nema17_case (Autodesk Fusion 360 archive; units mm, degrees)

design "final_assemble_winch+nemacase" references "Nema 17-1", "winch_final"
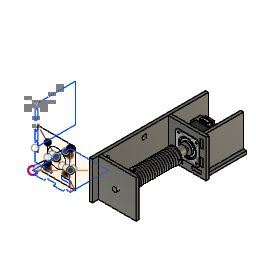
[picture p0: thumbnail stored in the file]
sketch "Sketch1" plane through (0, 0, 0) normal (0, 1, 0) x axis (1, 0, 0)
  line L1 (-32.5, 32.5) -> (32.5, 32.5)
  line L2 (32.5, -32.5) -> (-32.5, -32.5)
  line L3 (32.5, 32.5) -> (32.5, -32.5)
  line L4 (-32.5, -32.5) -> (32.5, 32.5)
  line L5 (32.5, -32.5) -> (-32.5, 32.5)
  line L6 (-15.5, -15.5) -> (-15.5, 0)
  line L7 (0, -3) -> (0, 0)
  line L8 (-3.2, 0) -> (0, 0)
  line L9 (-37.5, -24.375) -> (-32.5, -24.375)
  line L10 (-37.5, -8.125) -> (-37.5, -24.375)
  line L11 (-32.5, -8.125) -> (-37.5, -8.125)
  line L12 (-37.5, 8.125) -> (-37.5, 24.375)
  line L13 (-37.5, 24.375) -> (-32.5, 24.375)
  line L14 (-32.5, 8.125) -> (-37.5, 8.125)
  line L15 (22.5, -15.5) -> (15.5, -15.5)
  line L16 (22.5, 32.5) -> (22.5, -32.5)
  line L17 (-15.5, 22.5) -> (-15.5, 15.5)
  line L18 (-32.5, -32.5) -> (-32.5, -24.375)
  line L19 (-32.5, 24.375) -> (-32.5, 32.5)
  line L20 (-32.5, -8.125) -> (-32.5, 8.125)
  circle C1 centre (0, 0) radius 15.5
  circle C2 centre (-15.5, -15.5) radius 1.5
  circle C3 centre (-15.5, 15.5) radius 1.5
  circle C4 centre (15.5, 15.5) radius 1.5
  circle C5 centre (15.5, -15.5) radius 1.5
  point P6 (0, 0)
  point P1 (0, 0)
  point P7 (0, 0)
  point P8 (-15.5, 0)
  point P9 (-15.5, -15.5)
  point P10 (-15.5, -15.5)
  point P11 (0, 0)
  point P13 (0, 0)
  point P18 (-32.5, -24.375)
  point P24 (-32.5, 24.375)
  point P19 (-37.5, -24.375)
  point P22 (-37.5, 24.375)
  point P20 (-37.5, -8.125)
  point P23 (-37.5, 8.125)
  point P21 (-32.5, -8.125)
  point P25 (-32.5, 8.125)
  point P17 (15.5, -15.5)
  point P26 (15.5, -15.5)
  point P28 (22.5, -32.5)
  point P29 (22.5, 32.5)
  point P15 (-15.5, 15.5)
  point P30 (-15.5, 15.5)
  point P4 (-32.5, -32.5)
  point P5 (32.5, -32.5)
  point P2 (32.5, 32.5)
  point P27 (22.5, -15.5)
  point P3 (-32.5, 32.5)
  point P31 (-15.5, 22.5)
  perpendicular L1 L19
  parallel L1 L2
  parallel L3 L19
  horizontal L1
  coincident L4 P6
  coincident L5 P6
  coincident P1 P6
  coincident P1 P7
  coincident C1 P8
  tangent C1 L6
  parallel L6 L19
  coincident P9 P10
  coincident P1 P11
  vertical L7
  coincident P1 P13
  perpendicular L7 L8
  symmetric C2 L8 C3
  symmetric L7 C3 C4
  symmetric C2 L7 C5
  coincident P18 L19
  perpendicular L9 L19
  perpendicular L9 L10
  perpendicular L11 L19
  symmetric L8 P18 P24
  symmetric L8 P19 P22
  symmetric L8 P20 P23
  symmetric L8 P21 P25
  coincident P17 P26
  horizontal L15
  coincident L2 P28
  coincident L1 P29
  perpendicular L1 L16
  coincident P15 P30
  vertical L17
  collinear L18 L19
  collinear L19 L20
  dimension "d1" distance P4 P5 = 65
  dimension "d2" distance P2 P5 = 65
  dimension "d3" diameter C1 = 31
  dimension "d4" distance P8 P9 = 15.5 (= "( 31 / 2 ) * 1 mm")
  dimension "d5" diameter C2 = 3
  dimension "d7" distance P19 P20 = 16.25
  dimension "d8" distance P26 P27 P3 = 7
  dimension "d9" distance P30 P31 = 7
  dimension "d27" distance P3 = 55
  dimension "d113" distance P3 = 4.4
extrude "Extrude4" new body sketch "Sketch1" profile of L1 L20 L2 L3 C1 L6 C2 C3 C4 C5 L9 L10 L11 L12 L13 L14 L15 L16 along normal blind 5
sketch "Sketch2" plane through (0, 0, 0) normal (0, 1, 0) x axis (1, 0, 0)
sketch "Sketch3" plane through (0, 0, 0) normal (0, 0, 1) x axis (1, 0, 0)
  line L1 (-2.1, 25.8) -> (-2.1, -39.2)
  line L2 (62.9, 25.8) -> (-2.1, 25.8)
  line L3 (62.9, -39.2) -> (62.9, 25.8)
  line L4 (-2.1, 25.8) -> (62.9, -39.2)
  line L5 (62.9, 25.8) -> (-2.1, -39.2)
  line L6 (22.275, -39.2) -> (22.275, -44.2)
  line L7 (6.025, -44.2) -> (22.275, -44.2)
  line L8 (6.025, -39.2) -> (6.025, -44.2)
  line L9 (54.775, -39.2) -> (54.775, -44.2)
  line L10 (54.775, -44.2) -> (38.525, -44.2)
  line L11 (38.525, -39.2) -> (38.525, -44.2)
  line L12 (54.775, -39.2) -> (62.9, -39.2)
  line L13 (22.275, -39.2) -> (38.525, -39.2)
  line L14 (-2.1, -39.2) -> (6.025, -39.2)
  point P6 (30.4, -6.7)
  point P8 (22.275, -39.2)
  point P10 (6.025, -39.2)
  point P4 (-2.1, 25.8)
  point P5 (62.9, 25.8)
  point P3 (-2.1, -39.2)
  point P7 (22.275, -44.2)
  point P9 (6.025, -44.2)
  perpendicular L1 L12
  parallel L2 L12
  parallel L1 L3
  horizontal L12
  coincident L4 P6
  coincident L5 P6
  coincident P8 L12
  perpendicular L6 L12
  perpendicular L6 L7
  coincident P10 L12
  perpendicular L8 L12
  collinear L12 L13
  collinear L13 L14
  dimension "d10" distance P4 P5 = 65
  dimension "d11" distance P3 P4 = 65
  dimension "d14" distance P7 P9 = 16.25
sketch "Sketch4" plane through (0, 0, 0) normal (0, 1, 0) x axis (1, 0, 0)
  line L1 (-8.125, 22.5) -> (-8.125, 27.15)
  line L2 (-24.375, 27.15) -> (-8.125, 27.15)
  line L3 (-24.375, 22.5) -> (-24.375, 27.15)
  line L4 (24.375, 22.5) -> (24.375, 27.15)
  line L5 (24.375, 27.15) -> (8.125, 27.15)
  line L6 (8.125, 22.5) -> (8.125, 27.15)
  line L7 (24.375, 22.5) -> (8.125, 22.5)
  line L8 (-24.375, 22.5) -> (-8.125, 22.5)
  point P2 (-8.125, 27.15)
  point P4 (-24.375, 27.15)
  perpendicular L1 L2
  perpendicular L1 L8
  dimension "d17" distance P2 P4 = 16.25
extrude "Extrude5" cut sketch "Sketch4" along normal blind 5
sketch "Sketch5" plane through (0, 0, 0) normal (0, 0, 1) x axis (1, 0, 0)
  line L1 (23.4, -6.7) -> (30.4, -6.7)
  line L2 (30.4, -1.9) -> (30.4, -6.7)
  line L3 (-8.5404, 1.425) -> (-8.5404, -6.7)
  line L4 (-2.1, 25.8) -> (-2.1, -39.2)
  line L5 (-7.1, 1.425) -> (-2.1, 1.425)
  line L6 (-7.1, 17.675) -> (-7.1, 1.425)
  line L7 (-2.1, 17.675) -> (-7.1, 17.675)
  line L8 (16.3, -6.7) -> (30.4, -6.7)
  line L9 (-2.1, -31.075) -> (-7.1, -31.075)
  line L10 (-7.1, -31.075) -> (-7.1, -14.825)
  line L11 (-7.1, -14.825) -> (-2.1, -14.825)
  line L12 (-2.1, 17.675) -> (-2.1, 25.8)
  line L13 (-2.1, -14.825) -> (-2.1, 1.425)
  point P2 (30.4, -6.7)
  point P3 (30.4, -6.7)
  point P5 (30.4, -6.7)
  point P11 (-2.1, 1.425)
  point P14 (-2.1, 17.675)
  point P19 (-2.1, -14.825)
  point P12 (-7.1, 1.425)
  point P18 (-7.1, -14.825)
  point P13 (-7.1, 17.675)
  point P16 (-7.1, -31.075)
  point P17 (-2.1, -31.075)
  point P10 (-2.1, 25.8)
  point P20 (-2.1, 25.8)
  point P7 (-8.5404, -6.7)
  point P8 (-8.5404, 1.425)
  coincident P2 P3
  horizontal L1
  coincident P2 P5
  perpendicular L1 L2
  perpendicular L1 L3
  coincident L4 P11
  perpendicular L3 L5
  perpendicular L5 L6
  coincident L4 P14
  perpendicular L4 L7
  perpendicular L2 L8
  symmetric P11 L8 P19
  symmetric P12 L8 P18
  symmetric P13 L8 P16
  symmetric P14 L8 P17
  coincident P10 P20
  collinear L12 L13
  dimension "d18" distance P7 P8 = 8.125
  dimension "d19" distance P11 P12 = 5
  dimension "d20" distance P12 P13 = 16.25
sketch "Sketch6" plane through (0, 0, 0) normal (1, 0, 0) x axis (0, 1, 0)
sketch "Sketch7" plane through (0, 0, 0) normal (0, 0, 1) x axis (1, 0, 0)
sketch "Sketch8" plane through (0, 0, 0) normal (1, 0, 0) x axis (0, 1, 0)
  line L1 (-32.4958, 33.4881) -> (32.5042, 33.4881)
  line L2 (32.5042, 98.4881) -> (-32.4958, 98.4881)
  line L3 (32.5042, 33.4881) -> (32.5042, 98.4881)
  line L4 (-37.1458, 33.4881) -> (-32.4958, 33.4881)
  line L5 (-32.4958, 98.4881) -> (-37.1458, 98.4881)
  line L6 (-37.1458, 74.1131) -> (-32.4958, 74.1131)
  line L7 (-37.1458, 90.3631) -> (-32.4958, 90.3631)
  line L8 (-37.1458, 57.8631) -> (-32.4958, 57.8631)
  line L9 (-37.1458, 41.6131) -> (-32.4958, 41.6131)
  line L10 (-32.4958, 57.8631) -> (-32.4958, 41.6131)
  line L11 (-32.4958, 90.3631) -> (-32.4958, 74.1131)
  line L12 (-37.1458, 57.8631) -> (-37.1458, 41.6131)
  line L13 (-37.1458, 90.3631) -> (-37.1458, 74.1131)
  point P8 (-32.4958, 74.1131)
  point P10 (-32.4958, 90.3631)
  point P11 (-37.1458, 90.3631)
  point P4 (-32.4958, 98.4881)
  point P5 (32.5042, 98.4881)
  point P3 (-32.4958, 33.4881)
  point P6 (-37.1458, 33.4881)
  point P7 (-37.1458, 98.4881)
  perpendicular L1 L10
  parallel L1 L2
  parallel L3 L10
  horizontal L1
  perpendicular L4 L10
  perpendicular L4 L12
  coincident P8 L10
  perpendicular L6 L12
  coincident P10 L10
  coincident P11 L12
  perpendicular L7 L12
  collinear L10 L11
  collinear L12 L13
  dimension "d21" distance P4 P5 = 65
  dimension "d22" distance P3 P4 = 65
  dimension "d23" distance P3 P6 = 4.65
  dimension "d24" distance P6 P7 = 65
sketch "Sketch9" plane through (0, 0, 0) normal (0, 1, 0) x axis (1, 0, 0)
sketch "Sketch10" plane through (0, 0.0042, 65.9881) normal (1, 0, 0) x axis (0, 1, 0)
  line L1 (32.5, 32.5) -> (-32.5, 32.5)
  line L2 (0, -22.5) -> (0, 32.5)
  line L3 (32.5, -32.5) -> (32.5, 32.5)
  line L4 (24.375, -22.5) -> (8.125, -22.5)
  line L5 (-8.125, -22.5) -> (-8.125, -27.15)
  line L6 (-24.375, -27.15) -> (-8.125, -27.15)
  line L7 (-24.375, -22.5) -> (-24.375, -27.15)
  line L8 (24.375, -22.5) -> (24.375, -27.15)
  line L9 (24.375, -27.15) -> (8.125, -27.15)
  line L10 (8.125, -22.5) -> (8.125, -27.15)
  line L11 (-24.375, -22.5) -> (-8.125, -22.5)
  line L12 (-32.5, -8.125) -> (-32.5, -24.375)
  point P4 (0, 32.5)
  point P8 (-8.125, -27.15)
  point P14 (8.125, -27.15)
  point P9 (-8.125, -22.5)
  point P15 (8.125, -22.5)
  point P10 (-24.375, -27.15)
  point P12 (24.375, -27.15)
  point P11 (-24.375, -22.5)
  point P13 (24.375, -22.5)
  point P5 (0, -22.5)
  midpoint L1 P4
  perpendicular L1 L2
  perpendicular L2 L4
  perpendicular L4 L5
  perpendicular L5 L6
  perpendicular L4 L7
  symmetric L2 P8 P14
  symmetric L2 P9 P15
  symmetric L2 P10 P12
  symmetric L2 P11 P13
  dimension "d27" distance P4 P5 = 55
  dimension "d31" distance P8 P10 = 16.25
extrude "Extrude2" new body sketch "Sketch10" + "Sketch8" profile of S2:L11 S2:L13 S2:L6 S2:L7 S2:L8 S2:L9 S1:L4 S1:L5 S1:L6 S1:L7 S1:L8 S1:L9 S1:L10 S1:L11 blind 5
sketch "Sketch12" plane through (0, 0, 0) normal (1, 0, 0) x axis (0, 1, 0)
  line L1 (94.4234, 33.9841) -> (159.4234, 33.9841)
  line L2 (94.4234, 88.9841) -> (94.4234, 33.9841)
  line L3 (159.4234, 88.9841) -> (94.4234, 88.9841)
  line L4 (159.4234, 33.9841) -> (159.4234, 88.9841)
  point P3 (94.4234, 33.9841)
  point P4 (94.4234, 88.9841)
  point P2 (159.4234, 33.9841)
  perpendicular L1 L2
  parallel L1 L3
  parallel L2 L4
  horizontal L1
  dimension "d32" distance P3 P4 = 55
  dimension "d33" distance P2 P3 = 65
sketch "Sketch13" plane through (0, 0, 0) normal (1, 0, 0) x axis (0, 1, 0)
  line L1 (94.4234, 88.9841) -> (94.4234, 33.9841)
  line L2 (94.4234, 54.6091) -> (89.4234, 54.6091)
  line L3 (89.4234, 40.8591) -> (89.4234, 54.6091)
  line L4 (94.4234, 40.8591) -> (89.4234, 40.8591)
  line L5 (89.4234, 82.1091) -> (89.4234, 68.3591)
  line L6 (94.4234, 68.3591) -> (89.4234, 68.3591)
  line L7 (94.4234, 82.1091) -> (89.4234, 82.1091)
  line L8 (94.4234, 40.8591) -> (94.4234, 33.9841)
  line L9 (94.4234, 68.3591) -> (94.4234, 54.6091)
  line L10 (94.4234, 88.9841) -> (94.4234, 82.1091)
  point P5 (94.4234, 54.6091)
  point P7 (94.4234, 40.8591)
  point P2 (94.4234, 33.9841)
  point P12 (94.4234, 33.9841)
  point P3 (94.4234, 88.9841)
  point P13 (94.4234, 88.9841)
  point P4 (89.4234, 54.6091)
  point P6 (89.4234, 40.8591)
  coincident L1 P5
  perpendicular L1 L2
  perpendicular L2 L3
  coincident L1 P7
  perpendicular L1 L4
  coincident P2 P12
  perpendicular L6 L9
  coincident P3 P13
  perpendicular L7 L10
  dimension "d36" distance P4 P6 = 13.75
sketch "Sketch14" plane through (0, 0, 0) normal (0, 1, 0) x axis (1, 0, 0)
  line L1 (32.5, -32.5) -> (-32.5, -32.5)
  line L2 (22.5, 32.5) -> (22.5, -32.5)
  line L3 (27.15, -25.625) -> (22.5, -25.625)
  line L4 (27.15, -11.875) -> (22.5, -11.875)
  line L5 (27.15, 15.625) -> (22.5, 15.625)
  line L6 (27.15, 1.875) -> (22.5, 1.875)
  line L7 (27.15, -11.875) -> (27.15, -25.625)
  line L8 (27.15, 15.625) -> (27.15, 1.875)
  line L9 (22.5, 15.625) -> (22.5, 1.875)
  point P6 (22.5, -25.625)
  point P8 (22.5, -11.875)
  perpendicular L1 L7
  coincident L2 P6
  perpendicular L3 L7
  coincident L2 P8
  perpendicular L4 L7
  collinear L7 L8
  perpendicular L5 L9
  dimension "d38" distance L2 L7 = 4.65
extrude "Extrude6" cut sketch "Sketch14" profile of L8 L2 L3 L4 L5 L6 L9 along normal blind 5
sketch "Sketch15" plane through (0, 0, 0) normal (1, 0, 0) x axis (0, 1, 0)
  line L1 (126.9234, 46) -> (126.9234, 61.4841)
  line L2 (110.6, 61.4841) -> (126.9234, 61.4841)
  line L3 (94.4234, 33.9841) -> (159.4234, 33.9841)
  line L4 (118.7984, 33.9841) -> (118.7984, 28.9841)
  line L5 (102.5484, 28.9841) -> (118.7984, 28.9841)
  line L6 (102.5484, 33.9841) -> (102.5484, 28.9841)
  line L7 (151.2984, 33.9841) -> (151.2984, 28.9841)
  line L8 (151.2984, 28.9841) -> (135.0484, 28.9841)
  line L9 (135.0484, 33.9841) -> (135.0484, 28.9841)
  point P2 (126.9234, 61.4841)
  point P3 (126.9234, 61.4841)
  point P5 (126.9234, 61.4841)
  point P10 (118.7984, 33.9841)
  point P12 (102.5484, 33.9841)
  point P9 (118.7984, 28.9841)
  point P11 (102.5484, 28.9841)
  coincident P2 P3
  vertical L1
  coincident P2 P5
  perpendicular L1 L2
  coincident L3 P10
  perpendicular L3 L4
  perpendicular L4 L5
  coincident L3 P12
  perpendicular L3 L6
  dimension "d43" distance P9 P11 = 16.25
extrude "Extrude1" new body sketch "Sketch13" + "Sketch12" + "Sketch15" profile of S2:L1 S2:L2 S2:L3 S2:L4 S1:L1 S1:L2 S1:L3 S1:L4 S1:L5 S1:L6 S1:L7 S3:L3 S3:L4 S3:L5 S3:L6 S3:L7 S3:L8 S3:L9 blind 5
sketch "Sketch16" plane through (0, 0, 0) normal (0, 0, 1) x axis (1, 0, 0)
sketch "Sketch17" plane through (0, 0, 0) normal (0, 1, 0) x axis (1, 0, 0)
  line L1 (22.5, -15.5) -> (15.5, -15.5)
  line L2 (22.5, 32.5) -> (22.5, -32.5)
  line L3 (21.3, -15.5) -> (22.5, -15.5)
  point P2 (22.5, -15.5)
  point P7 (22.5, -15.5)
  point P8 (21.3, -15.5)
  coincident P2 P7
  coincident L1 P8
  perpendicular L2 L3
sketch "Sketch18" plane through (0, 0, 0) normal (0, 0, 1) x axis (1, 0, 0)
  line L1 (-2.1, 17.675) -> (-2.1, 25.8)
  line L2 (-2.1, 25.8) -> (-2.1, -39.2)
  line L3 (62.9, 25.8) -> (-2.1, 25.8)
  line L4 (54.775, -39.2) -> (62.9, -39.2)
  line L5 (62.9, -39.2) -> (62.9, 25.8)
  line L6 (52.9, 1.425) -> (57.55, 1.425)
  line L7 (52.9, 17.675) -> (57.55, 17.675)
  line L8 (52.9, -31.075) -> (57.55, -31.075)
  line L9 (57.55, -31.075) -> (57.55, -14.825)
  line L10 (52.9, -14.825) -> (57.55, -14.825)
  line L11 (52.9, 1.425) -> (52.9, 17.675)
  line L12 (52.9, -14.825) -> (52.9, -31.075)
  line L13 (57.55, 17.675) -> (57.55, 1.425)
  point P12 (57.55, 1.425)
  point P14 (57.55, 17.675)
  perpendicular L6 L11
  perpendicular L7 L11
  perpendicular L10 L12
  perpendicular L7 L13
  dimension "d48" distance P12 P14 = 16.25
extrude "Extrude12" new body sketch "Sketch5" profile of L4 L5 L6 L7 L9 L10 L11 along normal blind 5
extrude "Extrude9" new body sketch "Sketch18" profile of L11 L6 L7 L8 L9 L10 against normal blind 5
extrude "Extrude8" new body sketch "Sketch3" + "Sketch5" profile of S1:L14 S1:L1 S1:L2 S1:L3 S1:L6 S1:L7 S1:L8 S1:L9 S1:L10 S1:L11 S2:L4 S2:L5 S2:L6 S2:L7 S2:L9 S2:L10 S2:L11 blind 5
sketch "Sketch19" plane through (0, 0, 0) normal (0, 0, 1) x axis (1, 0, 0)
sketch "Sketch20" plane through (0, 0, 0) normal (1, 0, 0) x axis (0, 1, 0)
  line L1 (-78.1458, 98.4881) -> (-37.1458, 98.4881)
  line L2 (-78.1458, 90.9881) -> (-78.1458, 98.4881)
  line L3 (-37.1458, 33.4881) -> (-78.1458, 33.4881)
  line L4 (-150.8, 33.4881) -> (-78.1458, 33.4881)
  line L5 (-153.2, 98.4881) -> (-78.1458, 98.4881)
  line L6 (-37.1458, 33.4881) -> (-153.2, 33.4881)
  line L7 (-157.85, 98.4881) -> (-153.2, 98.4881)
  line L8 (-153.2, 33.4881) -> (-157.85, 33.4881)
  line L9 (-157.85, 74.1131) -> (-153.2, 74.1131)
  line L10 (-153.2, 90.4273) -> (-157.85, 90.4273)
  line L11 (-153.2, 41.549) -> (-157.85, 41.549)
  line L12 (-157.85, 57.8631) -> (-153.2, 57.8631)
  line L13 (-167.85, 98.4881) -> (-157.85, 98.4881)
  line L14 (-167.85, 33.4881) -> (-167.85, 98.4881)
  line L15 (-157.85, 33.4881) -> (-167.85, 33.4881)
  line L16 (-153.2, 74.1131) -> (-153.2, 90.4273)
  line L17 (-157.85, 74.1131) -> (-157.85, 90.4273)
  line L18 (-157.85, 41.549) -> (-157.85, 57.8631)
  line L19 (-153.2, 41.549) -> (-153.2, 57.8631)
  line L20 (-37.1458, 57.8631) -> (-37.1458, 41.6131)
  line L21 (32.5042, 98.4881) -> (32.5042, 33.4881)
  line L22 (-167.85, 98.4881) -> (32.5042, 98.4881)
  line L23 (32.5042, 33.4881) -> (-167.85, 33.4881)
  circle C1 centre (-78.1458, 86.9881) radius 4
  circle C2 centre (-78.1458, 44.9881) radius 4
  circle C3 centre (-142.1458, 86.9881) radius 4
  circle C4 centre (-142.1458, 44.9881) radius 4
  point P2 (-37.1458, 98.4881)
  point P3 (-37.1458, 98.4881)
  point P29 (32.5042, 33.4881)
  point P31 (32.5042, 33.4881)
  point P30 (32.5042, 98.4881)
  point P32 (32.5042, 98.4881)
  point P33 (32.5042, 33.4881)
  point P34 (-78.1458, 90.9881)
  point P4 (-78.1458, 98.4881)
  point P5 (-78.1458, 33.4881)
  point P7 (-78.1458, 86.9881)
  point P9 (-142.1458, 86.9881)
  point P12 (-153.2, 98.4881)
  point P13 (-153.2, 33.4881)
  point P15 (-157.85, 98.4881)
  point P16 (-157.85, 33.4881)
  point P25 (-167.85, 98.4881)
  point P26 (-167.85, 33.4881)
  coincident P2 P3
  perpendicular L1 L2
  perpendicular L2 L4
  perpendicular L2 L5
  perpendicular L7 L16
  perpendicular L7 L17
  perpendicular L9 L17
  perpendicular L10 L16
  perpendicular L13 L17
  perpendicular L13 L14
  collinear L17 L18
  coincident P29 P31
  coincident P30 P32
  perpendicular L3 L21
  perpendicular L14 L22
  coincident P29 P33
  perpendicular L21 L23
  coincident C1 P34
  dimension "d49" distance P3 P4 = 41
  dimension "d50" distance P4 P5 = 65
  dimension "d52" diameter C1 = 8
  dimension "d54" diameter C2 = 8
  dimension "d55" distance P7 P9 = 64
  dimension "d56" diameter C3 = 8
  dimension "d57" diameter C4 = 8
  dimension "d60" distance P12 P13 = 65
  dimension "d61" distance P12 P15 = 4.65
  dimension "d62" distance P15 P16 = 65
  dimension "d66" distance P15 P25 = 10
  dimension "d67" distance P25 P26 = 65
extrude "Extrude3" cut sketch "Sketch20" profile of L1 L3 C1 C2 C3 C4 L4 L5 L19 L6 L7 L18 L8 L9 L10 L11 L12 L13 L14 L15 L21 L22 L23 along normal blind 5
work_plane "WorkPlane1" AlongDistance 10
sketch "Sketch23" plane through (15, 124.4234, 58.9841) normal (1, 0, 0) x axis (0, 1, 0)
  line L1 (-30, 30) -> (35, 30)
  line L2 (35, 30) -> (35, -25)
  line L3 (35, -25) -> (26.875, -25)
  line L4 (26.875, -25) -> (26.875, -30)
  line L5 (26.875, -30) -> (10.625, -30)
  line L6 (10.625, -30) -> (10.625, -25)
  line L7 (10.625, -25) -> (-5.625, -25)
  line L8 (-5.625, -25) -> (-5.625, -30)
  line L9 (-30, 9.375) -> (-35, 9.375)
  line L10 (-30, -4.375) -> (-30, 9.375)
  line L11 (-35, -4.375) -> (-30, -4.375)
  line L12 (-35, -18.125) -> (-35, -4.375)
  line L13 (-30, -18.125) -> (-35, -18.125)
  line L14 (-30, -25) -> (-30, -18.125)
  line L15 (-21.875, -25) -> (-30, -25)
  line L16 (-21.875, -30) -> (-21.875, -25)
  line L17 (-5.625, -30) -> (-21.875, -30)
  line L18 (-5.625, -25) -> (-5.625, -30)
  line L19 (10.625, -25) -> (-5.625, -25)
  line L20 (10.625, -30) -> (10.625, -25)
  line L21 (26.875, -30) -> (10.625, -30)
  line L22 (26.875, -25) -> (26.875, -30)
  line L23 (35, -25) -> (26.875, -25)
  line L24 (35, 30) -> (35, -25)
  line L25 (-30, 30) -> (35, 30)
  line L26 (-30, 23.125) -> (-30, 30)
  line L27 (-35, 23.125) -> (-30, 23.125)
  line L28 (-35, 9.375) -> (-35, 23.125)
  line L29 (-21.875, -30) -> (-21.875, -25)
  line L30 (-21.875, -25) -> (-30, -25)
  line L31 (-30, -25) -> (35, -25)
  line L32 (-30, -18.125) -> (-35, -18.125)
  line L33 (-30, -4.375) -> (-30, 9.375)
  line L34 (-30, 9.375) -> (-35, 9.375)
  line L35 (-30, 30) -> (-30, -25)
  line L36 (-35, 23.125) -> (-30, 23.125)
  line L37 (-30, 23.125) -> (-30, 30)
sketch "Sketch21" plane through (0, 0, 0) normal (0, 1, 0) x axis (1, 0, 0)
  line L1 (71.9, 25.965) -> (136.9, 25.965)
  line L2 (136.9, -39.035) -> (71.9, -39.035)
  line L3 (136.9, 25.965) -> (136.9, -39.035)
  line L4 (66.9, 1.6) -> (71.9, 1.6)
  line L5 (66.9, 17.85) -> (66.9, 1.6)
  line L6 (71.9, 17.85) -> (66.9, 17.85)
  line L7 (66.9, -30.92) -> (66.9, -14.67)
  line L8 (66.9, -14.67) -> (71.9, -14.67)
  line L9 (71.9, -30.92) -> (66.9, -30.92)
  line L10 (71.9, -39.035) -> (71.9, -30.92)
  line L11 (71.9, 17.85) -> (71.9, 25.965)
  line L12 (71.9, -14.67) -> (71.9, 1.6)
  circle C1 centre (104.4, -6.535) radius 4
  point P6 (71.9, 1.6)
  point P4 (71.9, -39.035)
  point P5 (136.9, -39.035)
  point P3 (71.9, 25.965)
  point P7 (66.9, 1.6)
  point P8 (66.9, 17.85)
  perpendicular L1 L11
  parallel L1 L2
  parallel L3 L11
  horizontal L1
  coincident P6 L11
  perpendicular L4 L5
  perpendicular L6 L11
  collinear L10 L11
  collinear L11 L12
  dimension "d68" distance P4 P5 = 65
  dimension "d69" distance P3 P4 = 65
  dimension "d72" distance P6 P7 = 5
  dimension "d73" distance P7 P8 = 16.25
  dimension "d74" diameter C1 = 8
sketch "Sketch22" plane through (0, -110.1458, 65.9881) normal (1, 0, 0) x axis (0, 1, 0)
work_plane "WorkPlane2" AlongDistance 10
sketch "Sketch24" plane through (-2.5, -10, 0) normal (0, -1, 0) x axis (1, 0, 0)
  line L1 (25, 25.625) -> (25, 11.875)
  line L2 (25, -1.875) -> (25, -15.625)
  line L3 (-21.875, -22.5) -> (-21.875, -27.15)
  line L4
  line L5 (26.875, -22.5) -> (10.625, -22.5)
  line L6 (-30, 24.375) -> (-30, 32.5)
  line L7 (-35, 24.375) -> (-30, 24.375)
  line L8 (-35, 8.125) -> (-35, 24.375)
  line L9 (-30, 8.125) -> (-35, 8.125)
  line L10 (-30, -8.125) -> (-30, 8.125)
  line L11 (-35, -8.125) -> (-30, -8.125)
  line L12 (-35, -24.375) -> (-35, -8.125)
  line L13 (-30, -24.375) -> (-35, -24.375)
  line L14 (-30, -32.5) -> (-30, -24.375)
  line L15 (35, -32.5) -> (-30, -32.5)
  line L16 (35, 32.5) -> (35, -32.5)
  line L17 (-30, 32.5) -> (35, 32.5)
  line L18 (-5.625, -26.9) -> (-21.875, -26.9)
  line L19 (10.625, -26.9) -> (10.625, -22.5)
  line L20 (26.875, -26.9) -> (10.625, -26.9)
  line L21 (26.875, -22.5) -> (26.875, -26.9)
  line L22 (29.4, -15.625) -> (25, -15.625)
  line L23 (29.4, -1.875) -> (29.4, -15.625)
  line L24 (25, -1.875) -> (29.4, -1.875)
  line L25 (29.4, 11.875) -> (25, 11.875)
  line L26 (29.4, 25.625) -> (29.4, 11.875)
  line L27 (25, 25.625) -> (29.4, 25.625)
  line L28
  line L29 (-5.625, -22.5) -> (-5.625, -26.9)
  line L30 (10.625, -22.5) -> (10.625, -26.9)
  line L31 (26.875, -22.5) -> (26.875, -26.9)
  line L32 (25, -15.625) -> (29.4, -15.625)
  line L33 (25, -1.875) -> (29.4, -1.875)
  line L34 (25, 11.875) -> (29.4, 11.875)
  line L35 (25, 25.625) -> (29.4, 25.625)
  circle C1 centre (2.5, 0) radius 15.5
  circle C2 centre (-13, -15.5) radius 1.5
  circle C3 centre (18, -15.5) radius 1.5
  circle C4 centre (-13, 15.5) radius 1.5
  circle C5 centre (18, 15.5) radius 1.5
  point P9 (10.625, -22.5)
  point P30 (10.625, -22.5)
  point P10 (26.875, -22.5)
  point P33 (26.875, -22.5)
  point P5 (25, -15.625)
  point P34 (25, -15.625)
  point P4 (25, -1.875)
  point P37 (25, -1.875)
  point P2 (25, 11.875)
  point P38 (25, 11.875)
  point P3 (25, 25.625)
  point P41 (25, 25.625)
  point P8 (-21.875, -22.5)
  point P42 (-21.875, -22.5)
  point P6 (-5.625, -22.5)
  point P43 (-5.625, -22.5)
  point P44 (26.875, -22.5)
  point P45 (25, -1.875)
  point P46 (25, 11.875)
  point P47 (25, 25.625)
  point P28 (-21.875, -26.9)
  point P31 (10.625, -26.9)
  point P35 (29.4, -15.625)
  point P39 (29.4, 11.875)
  coincident P9 P30
  perpendicular L5 L19
  coincident P10 P33
  coincident P5 P34
  perpendicular L2 L22
  coincident P4 P37
  coincident P2 P38
  perpendicular L1 L25
  coincident P3 P41
  coincident P8 P42
  perpendicular L18 L28
  coincident P6 P43
  perpendicular L4 L29
  coincident P10 P44
  perpendicular L5 L31
  coincident P4 P45
  perpendicular L2 L33
  coincident P2 P46
  coincident P3 P47
  perpendicular L26 L35
  dimension "d113" distance P8 P28 = 4.4
  dimension "d114" distance P30 P31 = 4.4
  dimension "d115" distance P34 P35 = 4.4
  dimension "d116" distance P38 P39 = 4.4
work_plane "WorkPlane3" AlongDistance 10
sketch "Sketch25" plane through (27.9, -9.2, 15) normal (0, 0, 1) x axis (1, 0, 0)
sketch "Sketch26" plane through (0, 0, 0) normal (0, 0, 1) x axis (1, 0, 0)
  line L1 (-2.1, 17.675) -> (-7.1, 17.675)
  line L2 (-2.1, 17.675) -> (-2.1, 25.8)
  line L3 (-7.1, 1.425) -> (-7.1, 17.675)
  line L4 (-2.1, 1.425) -> (-7.1, 1.425)
  line L5 (-2.1, -14.825) -> (-2.1, 1.425)
  line L6 (-7.1, -14.825) -> (-2.1, -14.825)
  line L7 (-7.1, -31.075) -> (-7.1, -14.825)
  line L8 (-2.1, -31.075) -> (-7.1, -31.075)
  line L9 (-2.1, -39.2) -> (-2.1, -31.075)
  line L10 (6.025, -39.2) -> (6.025, -44.2)
  line L11 (6.025, -39.2) -> (-2.1, -39.2)
  line L12 (22.275, -44.2) -> (6.025, -44.2)
  line L13 (22.275, -39.2) -> (22.275, -44.2)
  line L14 (38.525, -39.2) -> (22.275, -39.2)
  line L15 (38.525, -44.2) -> (38.525, -39.2)
  line L16 (54.775, -44.2) -> (38.525, -44.2)
  line L17 (54.775, -39.2) -> (54.775, -44.2)
  line L18 (-2.1, 25.8) -> (62.9, 25.8)
  line L19 (52.9, 1.425) -> (57.55, 1.425)
  line L20 (52.9, 1.425) -> (52.9, 17.675)
  line L21 (52.9, -31.075) -> (57.55, -31.075)
  line L22 (52.9, -31.075) -> (52.9, -14.825)
  line L23 (62.9, 25.8) -> (62.9, -39.2)
  line L24 (62.9, -39.2) -> (54.775, -39.2)
  line L25 (57.3, 17.675) -> (52.9, 17.675)
  line L26 (57.3, 1.425) -> (57.3, 17.675)
  line L27 (52.9, 1.425) -> (57.3, 1.425)
  line L28 (57.55, -14.825) -> (52.9, -14.825)
  line L29 (57.3, -14.825) -> (52.9, -14.825)
  line L30 (57.3, -31.075) -> (57.3, -14.825)
  point P2 (-2.1, 25.8)
  point P6 (-2.1, 25.8)
  point P3 (-2.1, 17.675)
  point P7 (-2.1, 17.675)
  point P4 (-7.1, 17.675)
  point P9 (-7.1, 17.675)
  point P8 (-7.1, 1.425)
  point P10 (-7.1, 1.425)
  point P11 (-2.1, 1.425)
  point P12 (-2.1, 1.425)
  point P13 (-2.1, -14.825)
  point P14 (-2.1, -14.825)
  point P15 (-7.1, -14.825)
  point P16 (-7.1, -14.825)
  point P17 (-7.1, -31.075)
  point P18 (-7.1, -31.075)
  point P19 (-2.1, -31.075)
  point P20 (-2.1, -31.075)
  point P21 (-2.1, -39.2)
  point P22 (-2.1, -39.2)
  point P23 (6.025, -39.2)
  point P26 (6.025, -39.2)
  point P24 (6.025, -44.2)
  point P28 (6.025, -44.2)
  point P27 (22.275, -44.2)
  point P29 (22.275, -44.2)
  point P30 (22.275, -39.2)
  point P31 (22.275, -39.2)
  point P32 (38.525, -39.2)
  point P33 (38.525, -39.2)
  point P34 (38.525, -44.2)
  point P35 (38.525, -44.2)
  point P36 (54.775, -44.2)
  point P37 (54.775, -44.2)
  point P38 (54.775, -39.2)
  point P39 (54.775, -39.2)
  point P40 (62.9, 25.8)
  point P41 (62.9, 25.8)
  point P42 (-2.1, 25.8)
  point P43 (52.9, 17.675)
  point P47 (52.9, 17.675)
  point P44 (52.9, 1.425)
  point P48 (52.9, 1.425)
  point P50 (52.9, -14.825)
  point P54 (52.9, -14.825)
  point P51 (52.9, -31.075)
  point P55 (52.9, -31.075)
  point P57 (62.9, -39.2)
  point P58 (62.9, -39.2)
  point P59 (62.9, 25.8)
  point P60 (54.775, -39.2)
  point P61 (62.9, -39.2)
  point P63 (57.3, 1.425)
  point P66 (52.9, -14.825)
  point P67 (57.3, -14.825)
  point P68 (57.3, -31.075)
  point P62 (57.3, 17.675)
  coincident P2 P6
  coincident P3 P7
  coincident P4 P9
  coincident P8 P10
  coincident P11 P12
  coincident P13 P14
  coincident P15 P16
  coincident P17 P18
  coincident P19 P20
  coincident P21 P22
  coincident P23 P26
  coincident P24 P28
  coincident P27 P29
  coincident P30 P31
  coincident P32 P33
  coincident P34 P35
  coincident P36 P37
  coincident P38 P39
  coincident P40 P41
  coincident P2 P42
  coincident P43 P47
  coincident P44 P48
  coincident P50 P54
  coincident P51 P55
  coincident P57 P58
  coincident P40 P59
  coincident P38 P60
  coincident P57 P61
  perpendicular L20 L25
  coincident L19 P63
  perpendicular L19 L26
  coincident P50 P66
  coincident L28 P67
  coincident L21 P68
  perpendicular L21 L30
  dimension "d110" distance P47 P62 = 4.4
  dimension "d111" distance P66 P67 = 4.4
sketch "Sketch27" plane through (0, 0, 0) normal (1, 0, 0) x axis (0, 1, 0)
  line L1 (32.5042, 33.4881) -> (-167.85, 33.4881)
  line L2 (-167.85, 33.4881) -> (-167.85, 98.4881)
  line L3 (32.5042, 98.4881) -> (32.5042, 33.4881)
  line L4 (-167.85, 98.4881) -> (32.5042, 98.4881)
  line L5 (-157.85, 74.1131) -> (-153.2, 74.1131)
  line L6 (-153.2, 90.4273) -> (-153.2, 74.1131)
  line L7 (-157.6, 90.4273) -> (-153.2, 90.4273)
  line L8 (-153.2, 41.549) -> (-157.6, 41.549)
  line L9 (-153.2, 57.8631) -> (-153.2, 41.549)
  line L10 (-32.4958, 90.3631) -> (-32.4958, 74.1131)
  line L11 (-32.4958, 57.8631) -> (-32.4958, 41.6131)
  line L12 (-24.3708, 43.4881) -> (-8.1208, 43.4881)
  line L13 (8.1292, 43.4881) -> (24.3792, 43.4881)
  line L14 (-157.6, 90.4273) -> (-153.2, 90.4273)
  line L15 (-157.6, 74.1131) -> (-157.6, 90.4273)
  line L16 (-153.2, 74.1131) -> (-157.6, 74.1131)
  line L17 (-157.6, 57.8631) -> (-153.2, 57.8631)
  line L18 (-157.6, 41.549) -> (-157.6, 57.8631)
  line L19 (-153.2, 41.549) -> (-157.6, 41.549)
  line L20 (-34.8208, 90.3631) -> (-32.4958, 90.3631)
  line L21 (-36.8958, 74.1131) -> (-32.4958, 74.1131)
  line L22 (-36.8958, 90.3631) -> (-36.8958, 74.1131)
  line L23 (-32.4958, 90.3631) -> (-36.8958, 90.3631)
  line L24 (-36.8958, 57.8631) -> (-32.4958, 57.8631)
  line L25 (-36.8958, 41.6131) -> (-36.8958, 57.8631)
  line L26 (-32.4958, 41.6131) -> (-36.8958, 41.6131)
  line L27 (-24.3708, 39.0881) -> (-24.3708, 43.4881)
  line L28 (-8.1208, 39.0881) -> (-24.3708, 39.0881)
  line L29 (-8.1208, 43.4881) -> (-8.1208, 39.0881)
  line L30 (8.1292, 39.0881) -> (8.1292, 43.4881)
  line L31 (24.3792, 39.0881) -> (8.1292, 39.0881)
  line L32 (24.3792, 43.4881) -> (24.3792, 39.0881)
  line L33 (-25.5, 0) -> (-31.2, 0)
  line L34 (1.8, 0) -> (-31.2, 0)
  line L35 (-14.9, 0) -> (-31.2, 0)
  circle C1 centre (-142.1458, 86.9881) radius 4
  circle C2 centre (-142.1458, 44.9881) radius 4
  circle C3 centre (-78.1458, 86.9881) radius 4
  circle C4 centre (-78.1458, 44.9881) radius 4
  point P2 (-167.85, 98.4881)
  point P6 (-167.85, 98.4881)
  point P3 (-167.85, 33.4881)
  point P7 (-167.85, 33.4881)
  point P5 (32.5042, 33.4881)
  point P9 (32.5042, 33.4881)
  point P8 (32.5042, 98.4881)
  point P10 (32.5042, 98.4881)
  point P11 (-167.85, 98.4881)
  point P14 (-153.2, 74.1131)
  point P17 (-153.2, 74.1131)
  point P16 (-153.2, 90.4273)
  point P18 (-153.2, 90.4273)
  point P21 (-153.2, 41.549)
  point P22 (-153.2, 41.549)
  point P23 (-153.2, 57.8631)
  point P24 (-153.2, 57.8631)
  point P27 (-32.4958, 74.1131)
  point P28 (-32.4958, 74.1131)
  point P29 (-32.4958, 90.3631)
  point P30 (-32.4958, 90.3631)
  point P33 (-32.4958, 57.8631)
  point P35 (-32.4958, 57.8631)
  point P38 (-8.1208, 43.4881)
  point P39 (-8.1208, 43.4881)
  point P36 (-24.3708, 43.4881)
  point P40 (-24.3708, 43.4881)
  point P44 (24.3792, 43.4881)
  point P45 (24.3792, 43.4881)
  point P41 (8.1292, 43.4881)
  point P46 (8.1292, 43.4881)
  point P47 (-142.1458, 86.9881)
  point P48 (-142.1458, 86.9881)
  point P49 (-142.1458, 44.9881)
  point P50 (-142.1458, 44.9881)
  point P51 (-78.1458, 86.9881)
  point P52 (-78.1458, 86.9881)
  point P53 (-78.1458, 44.9881)
  point P54 (-78.1458, 44.9881)
  point P56 (-157.6, 74.1131)
  point P57 (-153.2, 74.1131)
  point P58 (-153.2, 57.8631)
  point P61 (-153.2, 41.549)
  point P66 (-32.4958, 90.3631)
  point P70 (-24.3708, 43.4881)
  point P73 (-8.1208, 43.4881)
  point P74 (8.1292, 43.4881)
  point P77 (24.3792, 43.4881)
  point P12 (-157.85, 90.4273)
  point P55 (-157.6, 90.4273)
  point P59 (-157.6, 57.8631)
  point P64 (-36.8958, 74.1131)
  point P67 (-36.8958, 57.8631)
  point P71 (-24.3708, 39.0881)
  point P75 (8.1292, 39.0881)
  coincident P2 P6
  coincident P3 P7
  coincident P5 P9
  coincident P8 P10
  coincident P2 P11
  coincident P14 P17
  coincident P16 P18
  coincident P21 P22
  coincident P23 P24
  coincident P27 P28
  coincident P29 P30
  coincident P33 P35
  coincident P38 P39
  coincident P36 P40
  coincident P44 P45
  coincident P41 P46
  coincident P47 P48
  coincident P49 P50
  coincident P51 P52
  coincident P53 P54
  perpendicular L6 L14
  coincident L5 P56
  perpendicular L5 L15
  coincident P14 P57
  coincident P23 P58
  perpendicular L9 L17
  perpendicular L8 L18
  coincident P21 P61
  coincident P29 P66
  perpendicular L11 L24
  coincident P36 P70
  perpendicular L12 L27
  perpendicular L27 L28
  coincident P38 P73
  perpendicular L12 L29
  coincident P41 P74
  perpendicular L13 L30
  perpendicular L30 L31
  coincident P44 P77
  perpendicular L13 L32
  horizontal L33
  horizontal L34
  horizontal L35
  dimension "d102" distance P12 P18 = 4.65
  dimension "d103" distance P18 P55 = 4.4
  dimension "d105" distance P58 P59 = 4.4
  dimension "d106" distance P28 P64 = 4.4
  dimension "d107" distance P35 P67 = 4.4
  dimension "d108" distance P70 P71 = 4.4
  dimension "d109" distance P74 P75 = 4.4
extrude "Extrude13" new body sketch "Sketch27" profile of L1 L2 L3 L4 L5 L6 L7 L8 L9 L10 L11 L12 L13 C1 C2 C3 C4 L14 L15 L16 L17 L18 L19 L20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 along normal blind 5
extrude "Extrude14" add sketch "Sketch21" profile of L1 L12 L2 L3 L4 L5 L6 L7 L8 L9 C1 along normal blind 5
component_from_bodies "Body->Comp1"
component_from_bodies "Body->Comp2"
component_from_bodies "Body->Comp3"
joint "Assemble1" alignAngle 0 alignOffsetX 0 alignOffsetY 0 alignOffsetZ 0
joint "Assemble2" alignAngle 0 alignOffsetX 0 alignOffsetY 0 alignOffsetZ 0
component_from_bodies "Body->Comp4"
joint "Assemble3" alignAngle 0 alignOffsetX 0 alignOffsetY 0 alignOffsetZ 0
extrude "Extrude15" new body sketch "Sketch26" along normal blind 5
component_from_bodies "Body->Comp5"
joint "Assemble4" alignAngle 0 alignOffsetX 0 alignOffsetY 0 alignOffsetZ 0
component_insert "Component Insert1"
position "Position1"
position "Position2"
sketch "Sketch28" plane through (163.0039, 0, 21.6511) normal (0, 1, 0) x axis (0, 0, 1)
  circle C1 centre (0, 0) radius 4
  point P1 (0, 0)
  point P2 (0, 0)
  coincident P1 P2
extrude "Extrude16" new body sketch "Sketch28" against normal blind 30
sketch "Sketch29" plane through (0, 73, 0) normal (0, 1, 0) x axis (-1, 0, 0)
  circle C1 centre (-163.0039, 21.6511) radius 4
  circle C2 centre (-163.0039, 21.6511) radius 13.1152
  circle C3 centre (-163.0039, 21.6511) radius 4
  concentric C1 C3
extrude "Extrude17" new body sketch "Sketch29" profile of C1 C3 along normal blind 10
sketch "Sketch30" plane through (0, 83, 0) normal (0, 1, 0) x axis (-1, 0, 0)
  circle C1 centre (-163.0039, 21.6511) radius 4
  circle C2 centre (-163.0039, 21.6511) radius 7
  concentric C1 C2
  dimension "d175" diameter C2 = 14
extrude "Extrude18" add sketch "Sketch30" along normal blind 15
component_from_bodies "Body->Comp6"
component_from_bodies "Body->Comp7"
component_insert "Component Insert2"
position "Position3"
joint "Assemble5" OffsetX 0 OffsetY 0 OffsetZ 0 AngleZ 0 alignAngle 180 alignOffsetX 0 alignOffsetY 0 alignOffsetZ 0
work_plane "WorkPlane4" AlongDistance -7.5
joint "Assemble6" OffsetX 0 OffsetY 0 OffsetZ 0 AngleZ 0 alignAngle 180 alignOffsetX 0 alignOffsetY 0 alignOffsetZ 0
joint "Assemble7" OffsetX 0 OffsetY 0 OffsetZ 0 AngleZ 0 alignAngle 0 alignOffsetX 0 alignOffsetY 0 alignOffsetZ 0
joint "Assemble8" OffsetX 0 OffsetY 0 OffsetZ 0 AngleZ 0 alignAngle 0 alignOffsetX 0 alignOffsetY 0 alignOffsetZ 0
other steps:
base_feature "Base Feature1"
base_feature "Base Feature1"
base_feature "Base Feature1"
base_feature "Base Feature1"
base_feature "Base Feature1"
base_feature "Base Feature1"
base_feature "Base Feature1"
create_component "CreateComponent1"
remove_body "RemoveBody1"
create_component "CreateComponent2"
remove_body "RemoveBody2"
create_component "CreateComponent3"
remove_body "RemoveBody3"
joint_origin "JointOrigin1" OffsetX 0 OffsetY 0 OffsetZ 0 AngleZ 0
joint_origin "JointOrigin1" OffsetX 0 OffsetY 0 OffsetZ 0 AngleZ 0
joint_origin "JointOrigin1" OffsetX 0 OffsetY 0 OffsetZ 0 AngleZ 0
joint_origin "JointOrigin2" OffsetX 0 OffsetY 0 OffsetZ 0 AngleZ 0
create_component "CreateComponent4"
remove_body "RemoveBody4"
joint_origin "JointOrigin1" OffsetX 0 OffsetY 0 OffsetZ 0 AngleZ 0
joint_origin "JointOrigin2" OffsetX 0 OffsetY 0 OffsetZ 0 AngleZ 0
create_component "CreateComponent5"
remove_body "RemoveBody5"
joint_origin "JointOrigin1" OffsetX 0 OffsetY 0 OffsetZ 0 AngleZ 0
joint_origin "JointOrigin3" OffsetX 0 OffsetY 0 OffsetZ 0 AngleZ 0
create_component "CreateComponent6"
remove_body "RemoveBody6"
create_component "CreateComponent7"
remove_body "RemoveBody7"
joint_origin "JointOrigin4" OffsetX 0 OffsetY 0 OffsetZ 0 AngleZ 0
joint_origin "JointOrigin1" OffsetX 0 OffsetY 0 OffsetZ 0 AngleZ 0
joint_origin "JointOrigin2" OffsetX 0 OffsetY 0 OffsetZ 0 AngleZ 0
joint_origin "JointOrigin1" OffsetX 0 OffsetY 0 OffsetZ 0 AngleZ 0

design "winch_final"
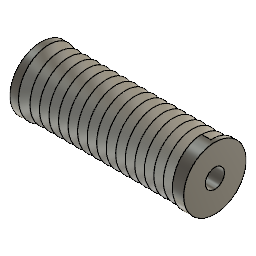
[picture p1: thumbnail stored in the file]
sketch "Sketch1" plane through (0, 0, 0) normal (1, 0, 0) x axis (0, 1, 0)
  circle C1 centre (0, 0) radius 4
  circle C2 centre (0, 0) radius 13.1152
  circle C3 centre (0, 0) radius 16
  circle C4 centre (0, 0) radius 13.1152
  circle C5 centre (0, 0) radius 13.1152
  circle C6 centre (0, 0) radius 13.1152
  circle C7 centre (0, 0) radius 13.1152
  circle C8 centre (0, 0) radius 13.1152
  circle C9 centre (0, 0) radius 13.1152
  circle C10 centre (0, 0) radius 13.1152
  circle C11 centre (0, 0) radius 13.1152
  circle C12 centre (0, 0) radius 13.1152
  circle C13 centre (0, 0) radius 13.1152
  circle C14 centre (0, 0) radius 13.1152
  circle C15 centre (0, 11) radius 1.25
  circle C16 centre (-2.9678, 10.5921) radius 1.25
  circle C17 centre (-5.7154, 9.3986) radius 1.25
  circle C18 centre (-8.0392, 7.5081) radius 1.25
  circle C19 centre (-9.7667, 5.0607) radius 1.25
  circle C20 centre (-10.7699, 2.238) radius 1.25
  circle C21 centre (-10.9744, -0.7507) radius 1.25
  circle C22 centre (-10.3649, -3.6837) radius 1.25
  circle C23 centre (-8.9867, -6.3435) radius 1.25
  circle C24 centre (-6.942, -8.5328) radius 1.25
  circle C25 centre (-4.3824, -10.0893) radius 1.25
  circle C26 centre (-1.4978, -10.8975) radius 1.25
  circle C27 centre (1.4978, -10.8975) radius 1.25
  circle C28 centre (4.3824, -10.0893) radius 1.25
  circle C29 centre (6.942, -8.5328) radius 1.25
  circle C30 centre (8.9867, -6.3435) radius 1.25
  circle C31 centre (10.3649, -3.6837) radius 1.25
  circle C32 centre (10.9744, -0.7507) radius 1.25
  circle C33 centre (10.7699, 2.238) radius 1.25
  circle C34 centre (9.7667, 5.0607) radius 1.25
  circle C35 centre (8.0392, 7.5081) radius 1.25
  circle C36 centre (5.7154, 9.3986) radius 1.25
  circle C37 centre (2.9678, 10.5921) radius 1.25
  point P1 (0, 0)
  point P2 (0, 0)
  coincident P1 P2
  concentric C1 C2
  concentric C1 C3
  dimension "d1" diameter C2 = 26.2304 (= "( ( 9.1152025 * 2 ) * 1 ) * 1 mm + 8 mm")
  dimension "d2" diameter C1 = 8
  dimension "d32" diameter C3 = 32
  dimension "d87" diameter C15 = 2.5
  dimension "d78" C-Pattern1-Angle = 360
  dimension "d93" C-Pattern3-Angle = 360
  dimension "d95" C-Pattern3-Angle = 360
extrude "Extrude1" new body sketch "Sketch1" profile of C1 C2 along normal blind 73
work_plane "WorkPlane2" AlongDistance -4
coil_primitive "CoilPrimitive7" Diameter 26.3 SectionSize 4 TaperAngle 0 Height -65 Pitch -4
sketch "Sketch46" plane through (73, 0, 0) normal (1, 0, 0) x axis (0, 1, 0)
  circle C1 centre (0, 0) radius 4
  circle C2 centre (0, 0) radius 17.5
  circle C3 centre (0, 0) radius 13.1152
  point P1 (0, 0)
  point P3 (0, 0)
  coincident P1 P3
extrude "Extrude18" cut sketch "Sketch1" profile of C33 along normal blind 4

design "Nema 17-1"
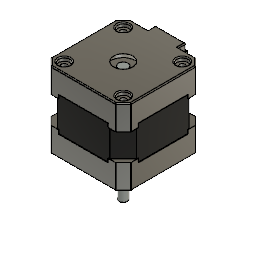
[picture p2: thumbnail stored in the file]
